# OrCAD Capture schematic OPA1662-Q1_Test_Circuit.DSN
size A; title: OPA1662-Q1 Dual, 3.3 nV/vHz Noise, 0.00006% THD+N, RRO, Bipo; rev: 1.4; note: Datasheet: SLOS805C   EVM: N/A
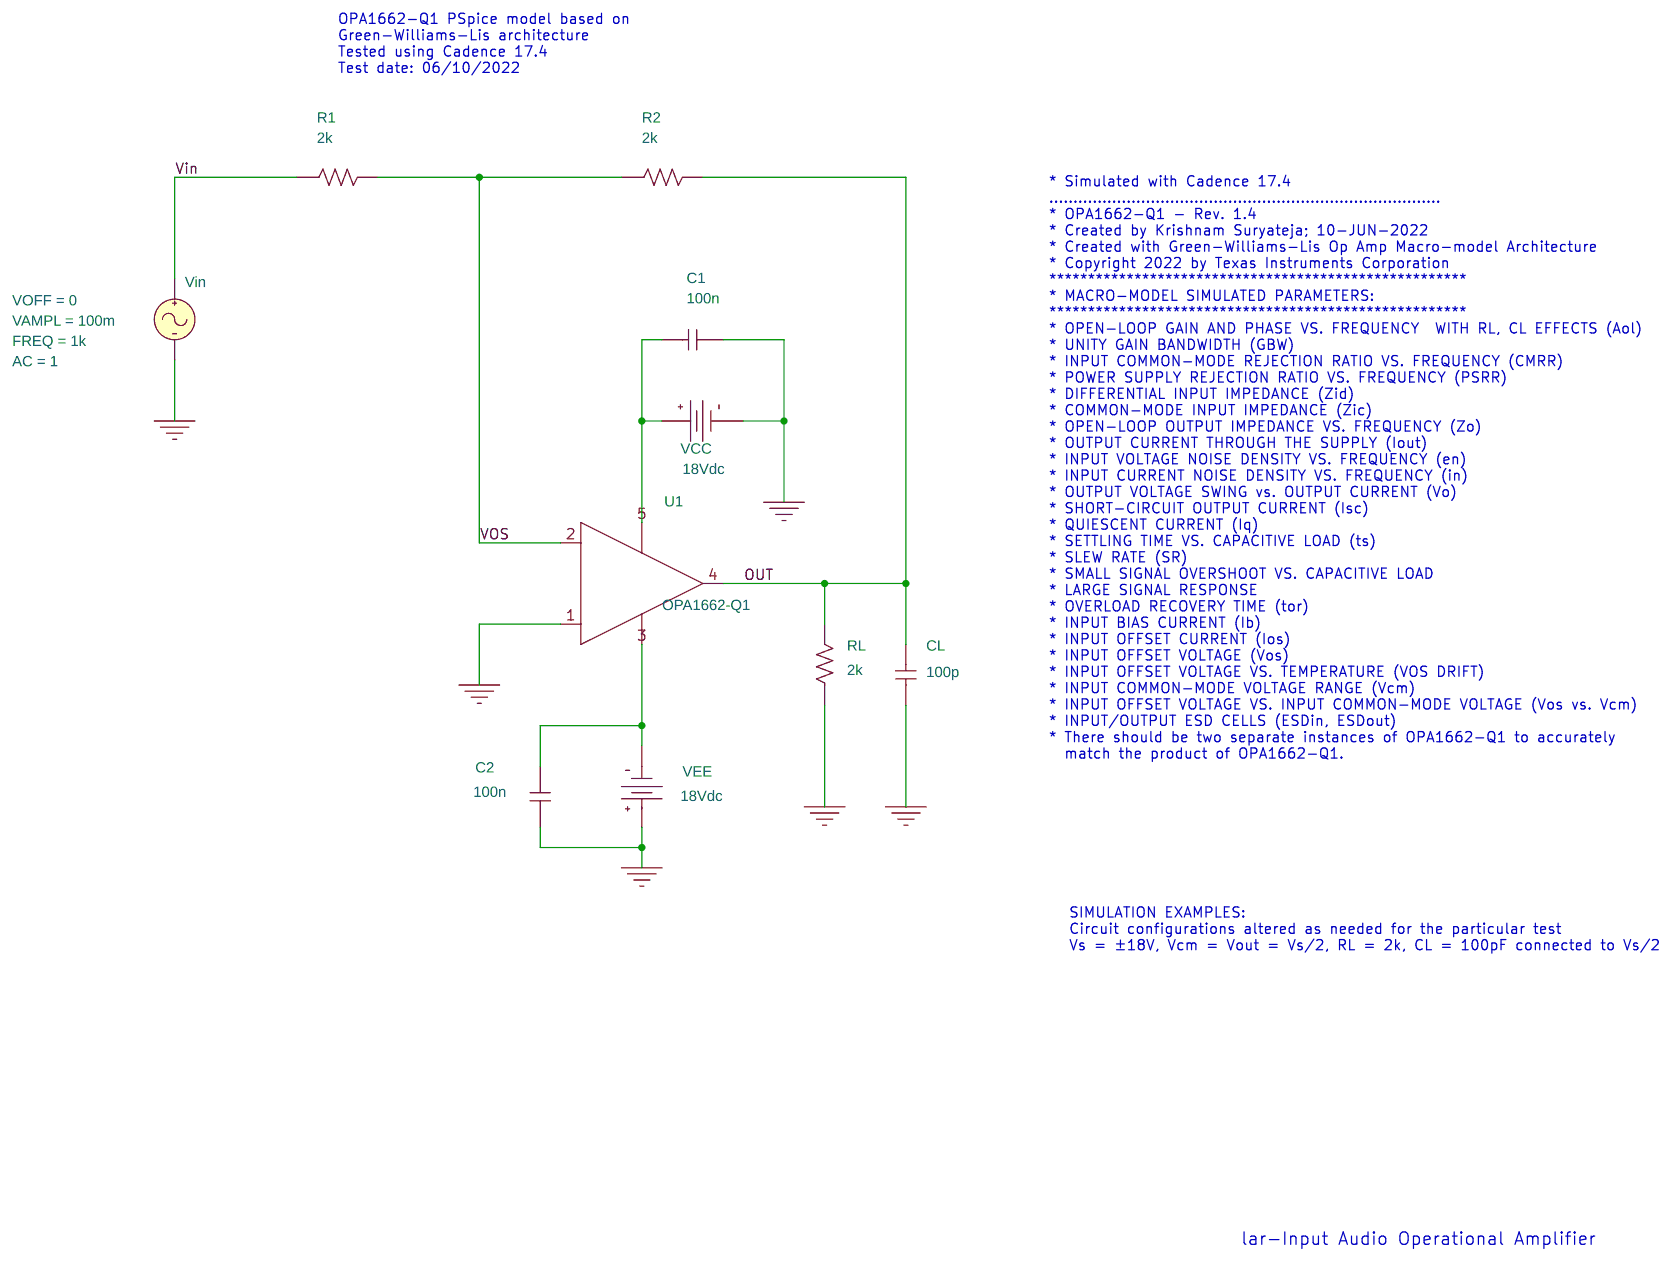
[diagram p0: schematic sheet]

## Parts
C1  100n  [cap196]
C2  100n  [cap196]
CL  100p  [cap196]
R1  2k  [AXRC05]
R2  2k  [AXRC05]
RL  2k  [AXRC05]
U1  OPA1662-Q1
VCC  VDC
VEE  VDC
Vin  VSIN

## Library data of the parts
C1 C2 CL = C
R1 R2 RL = R
U1 = OPA1662-Q1
VCC VEE = VDC: DC: 18Vdc
Vin = VSIN: AC: 1; FREQ: 1k; VAMPL: 100m; VOFF: 0

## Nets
Vin: R1.1 Vin.1(+)
0: C1.2 C2.1 CL.2 RL.1 U1.1(+) VCC.1(-) VEE.0(+) Vin.2(-)
OUT: CL.1 R2.2 RL.2 U1.4(OUT)
VOS: R1.2 R2.1 U1.2(-)
N27303: C1.1 U1.5(V+) VCC.0(+)
N27354: C2.2 U1.3(V-) VEE.1(-)

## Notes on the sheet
- OPA1662-Q1 PSpice model based on
  Green-Williams-Lis architecture
  Tested using Cadence 17.4
  Test date: 06/10/2022
- * Simulated with Cadence 17.4
  .................................................................................
  * OPA1662-Q1 - Rev. 1.4
  * Created by Krishnam Suryateja; 10-JUN-2022
  * Created with Green-Williams-Lis Op Amp Macro-model Architecture
  * Copyright 2022 by Texas Instruments Corporation
  ******************************************************
  * MACRO-MODEL SIMULATED PARAMETERS:
  ******************************************************
  * OPEN-LOOP GAIN AND PHASE VS. FREQUENCY  WITH RL, CL EFFECTS (Aol)
  * UNITY GAIN BANDWIDTH (GBW)
  * INPUT COMMON-MODE REJECTION RATIO VS. FREQUENCY (CMRR)
  * POWER SUPPLY REJECTION RATIO VS. FREQUENCY (PSRR)
  * DIFFERENTIAL INPUT IMPEDANCE (Zid)
  * COMMON-MODE INPUT IMPEDANCE (Zic)
  * OPEN-LOOP OUTPUT IMPEDANCE VS. FREQUENCY (Zo)
  * OUTPUT CURRENT THROUGH THE SUPPLY (Iout)
  * INPUT VOLTAGE NOISE DENSITY VS. FREQUENCY (en)
  * INPUT CURRENT NOISE DENSITY VS. FREQUENCY (in)
  * OUTPUT VOLTAGE SWING vs. OUTPUT CURRENT (Vo)
  * SHORT-CIRCUIT OUTPUT CURRENT (Isc)
  * QUIESCENT CURRENT (Iq)
  * SETTLING TIME VS. CAPACITIVE LOAD (ts)
  * SLEW RATE (SR)
  * SMALL SIGNAL OVERSHOOT VS. CAPACITIVE LOAD
  * LARGE SIGNAL RESPONSE
  * OVERLOAD RECOVERY TIME (tor)
  * INPUT BIAS CURRENT (Ib)
  * INPUT OFFSET CURRENT (Ios)
  * INPUT OFFSET VOLTAGE (Vos)
  * INPUT OFFSET VOLTAGE VS. TEMPERATURE (VOS DRIFT)
  * INPUT COMMON-MODE VOLTAGE RANGE (Vcm)
  * INPUT OFFSET VOLTAGE VS. INPUT COMMON-MODE VOLTAGE (Vos vs. Vcm)
  * INPUT/OUTPUT ESD CELLS (ESDin, ESDout)
  * There should be two separate instances of OPA1662-Q1 to accurately
    match the product of OPA1662-Q1.
- SIMULATION EXAMPLES:
  Circuit configurations altered as needed for the particular test
  Vs = ±18V, Vcm = Vout = Vs/2, RL = 2k, CL = 100pF connected to Vs/2
- lar-Input Audio Operational Amplifier
